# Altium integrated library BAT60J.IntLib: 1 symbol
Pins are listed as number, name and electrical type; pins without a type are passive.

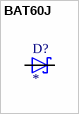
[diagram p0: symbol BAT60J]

## BAT60J
designator D?
Diode Schottky 10V 3A (DC) Surface Mount SOD-323; MF: STMicroelectronics; MP: BAT60J
footprint SOD323_ST
pins: A, C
